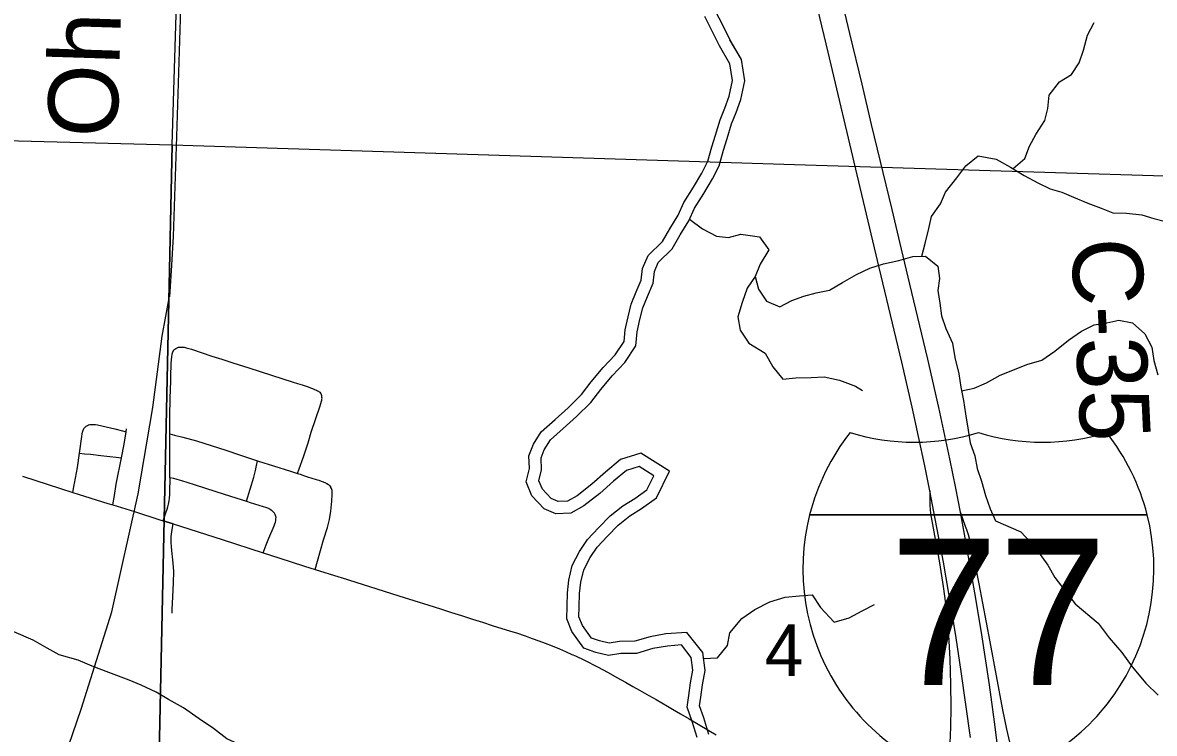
# Model space of a CAD drawing. Extents: x 0 to 34, y 0 to 22.
# Drawn here: x 29.042 to 29.958, y 20.143 to 20.718 of the extents above; entities that cross this region are included whole.
import ezdxf

# ---------------------------------------------------------------- set-up
doc = ezdxf.new("R2010")
doc.units = 0
for name, color, linetype in [('GM_X_Corporation', 7, 'Continuous'), ('GM_X_County_Road_Text', 7, 'Continuous'), ('GM_X_Interchange_Ramps', 7, 'Continuous'), ('GM_X_Interstate_Location', 7, 'Continuous'), ('GM_X_Interstate_Route', 7, 'Continuous'), ('GM_X_Interstate_Shield', 7, 'Continuous'), ('GM_X_Major_River', 7, 'Continuous'), ('GM_X_Minor_River', 7, 'Continuous'), ('GM_X_Rail_Line', 7, 'Continuous'), ('GM_X_Rail_Line_Text', 7, 'Continuous'), ('GM_X_Section_Text', 7, 'Continuous'), ('GM_X_State_Route', 7, 'Continuous'), ('GM_X_Township_Road', 7, 'Continuous')]:
    doc.layers.add(name, color=color, linetype=linetype)

msp = doc.modelspace()

# ---------------------------------------------------------------- linework, layer by layer
at = {"layer": 'GM_X_Corporation'}
for points in [[(29.17172, 20.9), (28.14745, 20.9), (28.1412, 20.64599), (28.15826, 20.64503), (29.16312, 20.61871)], [(28.15826, 20.64503), (29.16312, 20.61871), (29.14139, 19.60821), (28.13428, 19.63375)], [(29.16312, 20.61871), (29.66671, 20.60283), (30.17754, 20.58732), (30.18242, 20.58723), (30.15988, 19.58241), (29.14139, 19.60821)]]:
    msp.add_lwpolyline(points, close=True, dxfattribs=at)
at = {"layer": 'GM_X_Interchange_Ramps'}
for points in [[(29.77632, 20.33874), (29.77632, 20.33237), (29.77632, 20.32985), (29.77632, 20.32701), (29.77653, 20.32364), (29.77683, 20.32039), (29.7841, 20.28046), (29.78724, 20.26148), (29.78834, 20.25349), (29.78997, 20.23868), (29.79136, 20.22198), (29.79246, 20.20276), (29.79313, 20.18229), (29.79331, 20.16367), (29.79303, 20.14754), (29.79241, 20.13451)], [(29.84184, 20.13196), (29.83854, 20.14585), (29.83531, 20.16167), (29.8252, 20.21663), (29.81628, 20.2636), (29.81166, 20.28659), (29.8109, 20.29039), (29.80955, 20.29624), (29.80753, 20.3031), (29.80622, 20.30723), (29.80521, 20.31005), (29.80109, 20.3216)]]:
    msp.add_lwpolyline(points, dxfattribs=at)
at = {"layer": 'GM_X_Interstate_Route'}
for points in [[(29.77632, 20.33874), (29.77223, 20.35914), (29.76207, 20.40653), (29.75373, 20.44289), (29.73538, 20.51964), (29.71753, 20.59459), (29.69398, 20.69373), (29.67056, 20.79163), (29.64767, 20.88774), (29.64471, 20.9)], [(29.84542, 19.99124), (29.84478, 19.9992), (29.84449, 20.00246), (29.84059, 20.04748), (29.83748, 20.07838), (29.83297, 20.11788), (29.82873, 20.15177), (29.82454, 20.18192), (29.81814, 20.22429), (29.81289, 20.25616), (29.80444, 20.30387), (29.80109, 20.3216), (29.7974, 20.3411), (29.79259, 20.36484), (29.78366, 20.40612), (29.77461, 20.44548), (29.76021, 20.50592), (29.75342, 20.53433), (29.74589, 20.56638), (29.72925, 20.63524), (29.72152, 20.66788), (29.71159, 20.70896), (29.68623, 20.81534)], [(29.80922, 20.13915), (29.80183, 20.19271), (29.79775, 20.21975), (29.79396, 20.24306), (29.78732, 20.28102), (29.77969, 20.32196), (29.77632, 20.33874)]]:
    msp.add_lwpolyline(points, dxfattribs=at)
at = {"layer": 'GM_X_Interstate_Shield'}
for p, q in [((29.67903, 20.31937), (29.95229, 20.31937)), ((29.95229, 20.31937), (29.67903, 20.31937)), ((29.95229, 20.31937), (29.67903, 20.31937))]:
    msp.add_line(p, q, dxfattribs=at)
for centre, start, end in [((29.85117, 20.27584), 141.66896, 165.80665), ((29.76377, 20.55577), 253.00908, 286.99093), ((29.86755, 20.55577), 253.00908, 286.99093), ((29.78015, 20.27584), 14.19335, 38.33104), ((29.85117, 20.27584), 165.80665, 258.46304), ((29.78015, 20.27584), 281.53696, 14.19335)]:
    msp.add_arc(centre, 0.17756, start, end, dxfattribs=at)
at = {"layer": 'GM_X_Major_River'}
for points in [[(29.60608, 20.69878), (29.59992, 20.71123), (29.59415, 20.72254)], [(29.61489, 20.70315), (29.60871, 20.71564), (29.60293, 20.72696)], [(29.61473, 20.70348), (29.60871, 20.71564), (29.60293, 20.72696)], [(29.59753, 20.14155), (29.5934, 20.15517), (29.5899, 20.16477), (29.59097, 20.17184), (29.59237, 20.18197), (29.59439, 20.19348), (29.59267, 20.20789), (29.57967, 20.22432), (29.56266, 20.22301), (29.54993, 20.22081), (29.53749, 20.21711), (29.52527, 20.21698), (29.51671, 20.21557), (29.50884, 20.21754), (29.5024, 20.21969), (29.49531, 20.22972), (29.49229, 20.23696), (29.49252, 20.24509), (29.49279, 20.25573), (29.49373, 20.2649), (29.4962, 20.27487), (29.50137, 20.2848), (29.50696, 20.29321), (29.51531, 20.30211), (29.52418, 20.31117), (29.53342, 20.31852), (29.54296, 20.32454), (29.555, 20.33307), (29.56552, 20.35467), (29.54248, 20.36925), (29.52607, 20.36419), (29.51394, 20.354), (29.50281, 20.34415), (29.49091, 20.33483), (29.48309, 20.33053), (29.47554, 20.33022), (29.46998, 20.3326), (29.46271, 20.3403), (29.45997, 20.34699), (29.46211, 20.35589), (29.46167, 20.36544), (29.46426, 20.3721), (29.46934, 20.38004), (29.47962, 20.38916), (29.49031, 20.39892), (29.50182, 20.41026), (29.50993, 20.42093), (29.51932, 20.432), (29.52946, 20.44276), (29.53832, 20.45613), (29.53959, 20.46753), (29.54163, 20.47752), (29.54396, 20.48688), (29.54773, 20.49605), (29.55235, 20.50684), (29.5534, 20.51631), (29.5565, 20.52348), (29.5677, 20.53456), (29.57427, 20.54591), (29.5812, 20.55733), (29.58597, 20.56751), (29.59355, 20.57934), (29.60051, 20.5912), (29.60591, 20.60186), (29.60943, 20.61445), (29.61234, 20.62386), (29.61592, 20.63569), (29.6195, 20.64492), (29.62348, 20.6556), (29.62651, 20.67058), (29.62397, 20.68781), (29.61455, 20.70378)], [(29.59753, 20.14155), (29.5934, 20.15517), (29.5899, 20.16477), (29.59097, 20.17184), (29.59237, 20.18197), (29.59439, 20.19348), (29.59267, 20.20789), (29.57967, 20.22432), (29.56266, 20.22301), (29.54993, 20.22081), (29.53749, 20.21711), (29.52527, 20.21698), (29.51671, 20.21557), (29.50884, 20.21754), (29.5024, 20.21969), (29.49531, 20.22972), (29.49229, 20.23696), (29.49252, 20.24509), (29.49279, 20.25573), (29.49373, 20.2649), (29.4962, 20.27487), (29.50137, 20.2848), (29.50696, 20.29321), (29.51531, 20.30211), (29.52418, 20.31117), (29.53342, 20.31852), (29.54296, 20.32454), (29.555, 20.33307), (29.56552, 20.35467), (29.54248, 20.36925), (29.52607, 20.36419), (29.51394, 20.354), (29.50281, 20.34415), (29.49091, 20.33483), (29.48309, 20.33053), (29.47554, 20.33022), (29.46998, 20.3326), (29.46271, 20.3403), (29.45997, 20.34699), (29.46211, 20.35589), (29.46167, 20.36544), (29.46426, 20.3721), (29.46934, 20.38004), (29.47962, 20.38916), (29.49031, 20.39892), (29.50182, 20.41026), (29.50993, 20.42093), (29.51932, 20.432), (29.52946, 20.44276), (29.53832, 20.45613), (29.53959, 20.46753), (29.54163, 20.47752), (29.54396, 20.48688), (29.54773, 20.49605), (29.55235, 20.50684), (29.5534, 20.51631), (29.5565, 20.52348), (29.5677, 20.53456), (29.57427, 20.54591), (29.5812, 20.55733), (29.58597, 20.56751), (29.59355, 20.57934), (29.60051, 20.5912), (29.60591, 20.60186), (29.60943, 20.61445), (29.61234, 20.62386), (29.61592, 20.63569), (29.6195, 20.64492), (29.62348, 20.6556), (29.62651, 20.67058), (29.62397, 20.68781), (29.61473, 20.70348)], [(29.58796, 20.13922), (29.58407, 20.15206), (29.57981, 20.16376), (29.58124, 20.17325), (29.58266, 20.1835), (29.58446, 20.19375), (29.58324, 20.20397), (29.57521, 20.21411), (29.56388, 20.21324), (29.55217, 20.21122), (29.53898, 20.2073), (29.52612, 20.20716), (29.51631, 20.20554), (29.50608, 20.20809), (29.49622, 20.2114), (29.48666, 20.22494), (29.48241, 20.23512), (29.48269, 20.24536), (29.48298, 20.25635), (29.48402, 20.26659), (29.48694, 20.27837), (29.49289, 20.2898), (29.49923, 20.29934), (29.50822, 20.30891), (29.51759, 20.31848), (29.52772, 20.32655), (29.53749, 20.33271), (29.54726, 20.33964), (29.55283, 20.35106), (29.54105, 20.35852), (29.53087, 20.35538), (29.52036, 20.34656), (29.50911, 20.33659), (29.49634, 20.3266), (29.48581, 20.3208), (29.47372, 20.3203), (29.46423, 20.32437), (29.45431, 20.33488), (29.44967, 20.3462), (29.45223, 20.35684), (29.45176, 20.36706), (29.45545, 20.37658), (29.46179, 20.38649), (29.47304, 20.39647), (29.48355, 20.40605), (29.49441, 20.41677), (29.50226, 20.42709), (29.51199, 20.43856), (29.52173, 20.44889), (29.52881, 20.45958), (29.52987, 20.46907), (29.53204, 20.4797), (29.53459, 20.48996), (29.53866, 20.49986), (29.54274, 20.50937), (29.54379, 20.51886), (29.54823, 20.52914), (29.55985, 20.54063), (29.56581, 20.55093), (29.57252, 20.56199), (29.57734, 20.57227), (29.58517, 20.58448), (29.59187, 20.59592), (29.5967, 20.60545), (29.6, 20.61723), (29.60294, 20.62674), (29.60661, 20.6389), (29.61031, 20.64842), (29.614, 20.65831), (29.61654, 20.67084), (29.61453, 20.68447), (29.60608, 20.69878)]]:
    msp.add_lwpolyline(points, dxfattribs=at)
at = {"layer": 'GM_X_Minor_River'}
for points in [[(29.84373, 20.59957), (29.85337, 20.60775), (29.85706, 20.61764), (29.86227, 20.62717), (29.86935, 20.63861), (29.87191, 20.64811), (29.87295, 20.65912), (29.88117, 20.66982), (29.89095, 20.6756), (29.89729, 20.68515), (29.9006, 20.69541), (29.9039, 20.70758), (29.90947, 20.71787)], [(29.76996, 20.52869), (29.7727, 20.53906), (29.77562, 20.55122), (29.7778, 20.56072), (29.78489, 20.57102), (29.78897, 20.58054), (29.79831, 20.59201), (29.80541, 20.60194), (29.81555, 20.61), (29.82994, 20.60712), (29.84171, 20.6008), (29.85273, 20.59409), (29.86375, 20.58814), (29.87362, 20.58332), (29.8831, 20.58039), (29.89258, 20.57632), (29.90434, 20.57151), (29.91497, 20.56745), (29.92445, 20.56376), (29.93541, 20.5635), (29.9479, 20.56211), (29.95776, 20.55918), (29.96723, 20.55663)], [(29.58179, 20.55861), (29.59227, 20.55082), (29.60367, 20.54488), (29.6135, 20.54384), (29.62331, 20.5466), (29.63845, 20.54448), (29.6461, 20.53395), (29.63902, 20.52213), (29.63495, 20.51223), (29.63769, 20.50203), (29.6442, 20.49224), (29.65483, 20.4878), (29.66461, 20.49283), (29.67441, 20.49634), (29.68421, 20.4991), (29.69516, 20.50111), (29.70569, 20.50728), (29.71697, 20.51384), (29.72789, 20.51889), (29.73882, 20.52241), (29.75127, 20.52519), (29.76259, 20.52834), (29.77279, 20.52883), (29.78269, 20.52059), (29.78429, 20.51076), (29.78287, 20.50089), (29.78447, 20.49067), (29.78569, 20.48045), (29.78919, 20.47026), (29.79458, 20.45818), (29.79657, 20.44684), (29.79972, 20.4336), (29.80133, 20.42263), (29.80369, 20.41204), (29.8053, 20.40107), (29.8073, 20.38783), (29.80891, 20.37761), (29.81278, 20.36704), (29.81476, 20.35683), (29.81825, 20.34663), (29.82138, 20.33492), (29.82525, 20.32434), (29.8295, 20.31454), (29.84999, 20.30566), (29.86068, 20.29402), (29.87177, 20.2786), (29.87753, 20.2688), (29.88633, 20.25715), (29.89397, 20.24738), (29.91264, 20.23166), (29.92143, 20.22), (29.93175, 20.20798), (29.94016, 20.19632), (29.95124, 20.18317), (29.96116, 20.17343)], [(29.63495, 20.51223), (29.62861, 20.50269), (29.62455, 20.49128), (29.62088, 20.47949), (29.62286, 20.4689), (29.62976, 20.45836), (29.64306, 20.45016), (29.64921, 20.43923), (29.65724, 20.42909), (29.66781, 20.43033), (29.68029, 20.43046), (29.69087, 20.43095), (29.70336, 20.42843), (29.71626, 20.42364), (29.72196, 20.41991)], [(29.80198, 20.41969), (29.81229, 20.42198), (29.82209, 20.42626), (29.83337, 20.43244), (29.84354, 20.43633), (29.85484, 20.441), (29.86691, 20.44454), (29.87743, 20.45185), (29.88869, 20.46068), (29.89921, 20.46799), (29.90937, 20.47302), (29.91957, 20.47465), (29.92937, 20.47702), (29.94036, 20.47486), (29.95027, 20.46587), (29.95603, 20.45494), (29.95764, 20.44435), (29.96077, 20.43263)], [(29.59323, 20.20318), (29.60441, 20.20381), (29.61264, 20.21375), (29.61444, 20.224), (29.62416, 20.23547), (29.63469, 20.24278), (29.64673, 20.24897), (29.65917, 20.25288), (29.67088, 20.25376), (29.68108, 20.25463), (29.68797, 20.24447), (29.69904, 20.23246), (29.71111, 20.23599), (29.72164, 20.24179), (29.73143, 20.24682)], [(29.29784, 20.09451), (29.28739, 20.10046), (29.2741, 20.10752), (29.26385, 20.11196), (29.25324, 20.11526), (29.24109, 20.12082), (29.23159, 20.1264), (29.22172, 20.13161), (29.20729, 20.13827), (29.19664, 20.1465), (29.18485, 20.15434), (29.1723, 20.1633), (29.16014, 20.16999), (29.15026, 20.17595), (29.13811, 20.18151), (29.12825, 20.18557), (29.11194, 20.19185), (29.09828, 20.19701), (29.0869, 20.20182), (29.07174, 20.20621), (29.06186, 20.21141), (29.05046, 20.21811), (29.03491, 20.22477)]]:
    msp.add_lwpolyline(points, dxfattribs=at)
at = {"layer": 'GM_X_Rail_Line'}
for points in [[(29.16119, 20.49583), (29.16267, 20.51693), (29.16414, 20.54475), (29.16683, 20.62566), (29.17019, 20.729), (29.17207, 20.8052), (29.17449, 20.8724), (29.17535, 20.9)], [(28.87412, 19.5654), (29.06268, 20.08407), (29.08941, 20.1621), (29.11423, 20.24091), (29.13556, 20.33631), (29.14735, 20.40617), (29.15508, 20.46387), (29.16098, 20.49637)]]:
    msp.add_lwpolyline(points, dxfattribs=at)
at = {"layer": 'GM_X_State_Route'}
msp.add_line((29.1557, 20.31457), (29.16383, 20.31199), dxfattribs=at)
for points in [[(29.04181, 20.3506), (29.07258, 20.34076), (29.0827, 20.33759), (29.11112, 20.32868), (29.11497, 20.32748), (29.13246, 20.32201), (29.15316, 20.31537), (29.1557, 20.31457)], [(29.16383, 20.31199), (29.20352, 20.29945), (29.23674, 20.28876), (29.24952, 20.28465), (29.27016, 20.27796), (29.27887, 20.27523), (29.29801, 20.26921), (29.29992, 20.26861)], [(29.29992, 20.26861), (29.34657, 20.25379), (29.3709, 20.24627), (29.38034, 20.24328), (29.38914, 20.24048), (29.39735, 20.23783), (29.4062, 20.23504), (29.41419, 20.23251)], [(29.41419, 20.23251), (29.42218, 20.22997), (29.43699, 20.22529), (29.44173, 20.22383), (29.44875, 20.22139), (29.45458, 20.21937), (29.45978, 20.21742), (29.465, 20.21552), (29.47076, 20.21329), (29.47648, 20.21096), (29.48139, 20.20892), (29.48669, 20.20648), (29.48953, 20.20522), (29.49683, 20.2018), (29.50734, 20.19644), (29.51607, 20.19174), (29.52311, 20.18786), (29.53011, 20.18394), (29.53603, 20.18061), (29.54139, 20.17756), (29.54889, 20.17327), (29.55478, 20.16988), (29.56389, 20.16461), (29.56816, 20.16211), (29.57455, 20.15828), (29.58155, 20.15429), (29.59008, 20.14919), (29.6035, 20.14145)]]:
    msp.add_lwpolyline(points, dxfattribs=at)
at = {"layer": 'GM_X_Township_Road'}
for p, q in [((29.12576, 20.38656), (29.12617, 20.38893)), ((29.16383, 20.31199), (29.1557, 20.31457))]:
    msp.add_line(p, q, dxfattribs=at)
for points in [[(29.16527, 20.45345), (29.1661, 20.45406), (29.16704, 20.45463), (29.16808, 20.45503), (29.16939, 20.4552), (29.17026, 20.4552), (29.1714, 20.45513), (29.17271, 20.45496), (29.17449, 20.45457), (29.17869, 20.45334), (29.19523, 20.44783), (29.20322, 20.44526), (29.21213, 20.44237), (29.22507, 20.43827), (29.24349, 20.43245), (29.26102, 20.42669), (29.26458, 20.42555), (29.26818, 20.42451), (29.27159, 20.42345), (29.27329, 20.42286)], [(29.16108, 20.38482), (29.16108, 20.38644), (29.16118, 20.39888), (29.16159, 20.4138), (29.16197, 20.42748), (29.16202, 20.43121), (29.16228, 20.44178), (29.16275, 20.44745), (29.16302, 20.44913), (29.16335, 20.45037), (29.16366, 20.45131), (29.16406, 20.45215), (29.16456, 20.45285), (29.16527, 20.45345)], [(29.27329, 20.42286), (29.275, 20.42226), (29.27655, 20.42169), (29.27839, 20.42095), (29.27979, 20.42031), (29.28075, 20.41981), (29.28159, 20.41934), (29.28216, 20.41893), (29.28263, 20.41853), (29.28316, 20.41789)], [(29.26465, 20.35285), (29.26596, 20.3566), (29.26943, 20.36646), (29.27082, 20.3705), (29.27305, 20.37753), (29.27564, 20.38641), (29.28275, 20.4075), (29.28397, 20.41131), (29.28417, 20.41218), (29.28431, 20.41292), (29.28438, 20.41372), (29.28434, 20.4146), (29.28428, 20.41557), (29.28404, 20.41651), (29.28367, 20.41725), (29.28316, 20.41789)], [(29.08797, 20.36923), (29.08989, 20.38279), (29.09025, 20.38495), (29.09053, 20.38628), (29.09075, 20.38722), (29.09096, 20.3879), (29.09124, 20.38854), (29.09161, 20.38916), (29.0921, 20.3898), (29.09268, 20.39042), (29.0935, 20.39107)], [(29.0935, 20.39107), (29.09463, 20.39178), (29.09549, 20.39216), (29.09655, 20.3924), (29.09774, 20.39257), (29.09905, 20.39263), (29.10089, 20.39247), (29.10275, 20.39214), (29.1168, 20.38895), (29.12282, 20.38734), (29.12576, 20.38656)], [(29.12199, 20.36539), (29.12421, 20.37657), (29.12576, 20.38656)], [(29.16108, 20.38482), (29.16484, 20.38395), (29.17163, 20.38221), (29.18287, 20.37925), (29.20652, 20.37169), (29.21828, 20.36761), (29.22646, 20.36487), (29.23209, 20.36318)], [(29.16132, 20.34959), (29.16111, 20.36592), (29.16108, 20.38482)], [(29.0827, 20.33759), (29.08387, 20.34361), (29.08411, 20.34482), (29.08633, 20.35764), (29.08797, 20.36923)], [(29.08797, 20.36923), (29.09202, 20.36888), (29.09694, 20.36845), (29.10537, 20.36749), (29.11268, 20.36663), (29.11778, 20.36599), (29.12199, 20.36539)], [(29.11497, 20.32748), (29.1163, 20.33516), (29.11788, 20.34431), (29.11926, 20.35225), (29.1207, 20.35891), (29.12199, 20.36539)], [(29.22323, 20.33052), (29.22912, 20.34976), (29.23051, 20.35515), (29.23134, 20.35934), (29.23209, 20.36318)], [(29.23209, 20.36318), (29.23287, 20.36295), (29.24518, 20.35904), (29.25876, 20.35479), (29.26465, 20.35285)], [(29.1557, 20.31457), (29.15796, 20.32093), (29.159, 20.32386), (29.15962, 20.32595), (29.16015, 20.32806), (29.16064, 20.33063), (29.16092, 20.33296), (29.16117, 20.33579), (29.16132, 20.33855), (29.16133, 20.34851), (29.16132, 20.34959)], [(29.16132, 20.34959), (29.16411, 20.34897), (29.16697, 20.34821), (29.17068, 20.34711), (29.18077, 20.34396), (29.19852, 20.3382), (29.21035, 20.33438), (29.22323, 20.33052)], [(29.26465, 20.35285), (29.26667, 20.35218), (29.27015, 20.35105), (29.27269, 20.35027), (29.27624, 20.34911), (29.27952, 20.34806), (29.2819, 20.34734), (29.28372, 20.3467), (29.28525, 20.34614), (29.28711, 20.34532), (29.28835, 20.34472), (29.28955, 20.34393), (29.29045, 20.34312), (29.29137, 20.3421)], [(29.27887, 20.27523), (29.28077, 20.28185), (29.28569, 20.29908), (29.28877, 20.30908), (29.29035, 20.31568), (29.29147, 20.32238), (29.29234, 20.33034), (29.29262, 20.33583), (29.29262, 20.33728), (29.2926, 20.33815), (29.29251, 20.33917), (29.2923, 20.33996), (29.29204, 20.3408), (29.29137, 20.3421)], [(29.22323, 20.33052), (29.22631, 20.32948), (29.23684, 20.32625), (29.23856, 20.32568), (29.24035, 20.32502), (29.24143, 20.32451), (29.24251, 20.32391), (29.24349, 20.32317), (29.24441, 20.32236), (29.24512, 20.32158), (29.24588, 20.32062)], [(29.23674, 20.28876), (29.23926, 20.29524), (29.24126, 20.3004), (29.2457, 20.31058), (29.24629, 20.31214), (29.24666, 20.31355), (29.24686, 20.31454), (29.247, 20.31538), (29.24708, 20.31619), (29.24714, 20.31734), (29.24706, 20.31797), (29.24675, 20.31897), (29.24645, 20.3196), (29.24588, 20.32062)], [(29.16303, 20.23984), (29.16316, 20.24268), (29.16367, 20.25308), (29.16421, 20.26433), (29.16431, 20.27362), (29.16395, 20.28042), (29.16241, 20.29333), (29.16215, 20.29766), (29.16236, 20.30198), (29.16316, 20.3075), (29.16383, 20.31199)]]:
    msp.add_lwpolyline(points, dxfattribs=at)

# ---------------------------------------------------------------- texts
at = {"layer": 'GM_X_County_Road_Text'}
msp.add_text('C-35', height=0.056818, rotation=272.71182, dxfattribs=at).set_placement((29.89083, 20.54225))
at = {"layer": 'GM_X_Interstate_Location'}
for s in ['-', '.', ',']:
    msp.add_text(s, height=0.000189, dxfattribs=at).set_placement((29.81564, 20.24382))
msp.add_text('77', height=0.000189, rotation=0.00001, dxfattribs=at).set_placement((29.77694, 20.20461))
at = {"layer": 'GM_X_Interstate_Shield'}
msp.add_text('77', height=0.118371, dxfattribs=at).set_placement((29.74377, 20.18177))
at = {"layer": 'GM_X_Rail_Line_Text'}
msp.add_text('Ohio', height=0.056629, rotation=88.20228, dxfattribs=at).set_placement((29.11852, 20.62417))
at = {"layer": 'GM_X_Section_Text'}
msp.add_text('4', height=0.04186, rotation=0.00001, dxfattribs=at).set_placement((29.64278, 20.18887))

doc.saveas('drawing.dxf')
